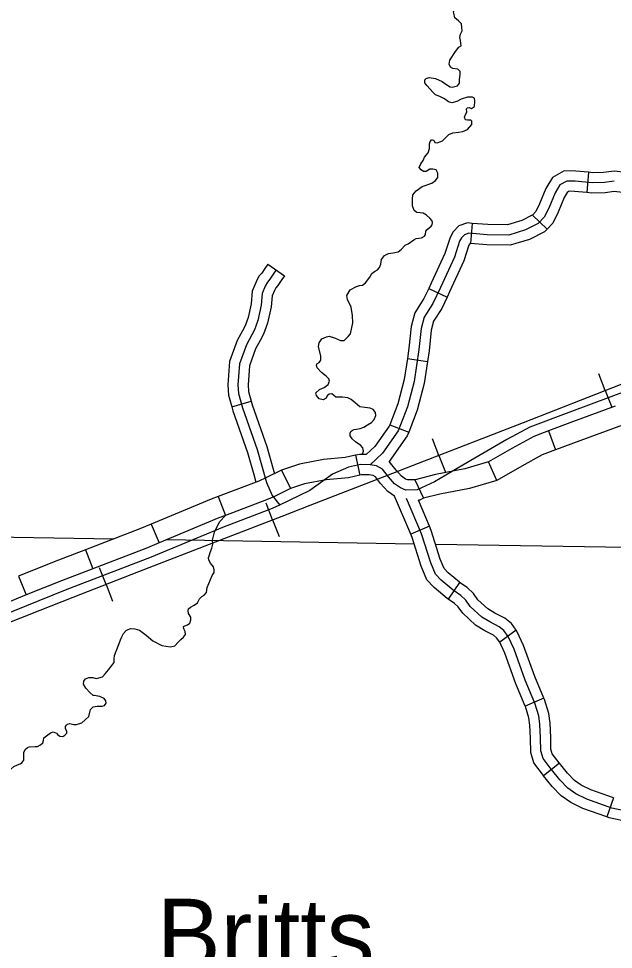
# Model space of a CAD drawing. Extents: x 8749 to 11879, y 13275 to 15339.
# Drawn here: x 10649.1 to 10737.1, y 13692.2 to 13830 of the extents above; entities that cross this region are included whole.
import ezdxf

# ---------------------------------------------------------------- set-up
doc = ezdxf.new("R2010")
doc.units = 0
for name, color, linetype in [('Level 25', 7, 'Continuous'), ('Level 32', 7, 'Continuous'), ('Level 35', 7, 'Continuous'), ('Level 40', 7, 'Continuous'), ('Level 45', 7, 'Continuous'), ('Level 5', 7, 'Continuous')]:
    doc.layers.add(name, color=color, linetype=linetype)

msp = doc.modelspace()

# ---------------------------------------------------------------- linework, layer by layer
at = {"layer": 'Level 32'}
for p, q in [((10733.4, 13807.23), (10733.14, 13804.24)), ((10725.11, 13800.9), (10727.28, 13798.83)), ((10716.19, 13799.68), (10715.95, 13796.69)), ((10709.78, 13790.04), (10712.49, 13788.76)), ((10706.63, 13779.7), (10709.6, 13779.25)), ((10704.02, 13769.85), (10706.82, 13768.77)), ((10727.47, 13768.95), (10728.52, 13766.14)), ((10698.95, 13765.36), (10699.61, 13762.43)), ((10688.02, 13763.15), (10689.33, 13760.43)), ((10707.74, 13761.71), (10709.02, 13759)), ((10678.65, 13759.26), (10679.71, 13756.45)), ((10668.75, 13755.17), (10669.9, 13752.41)), ((10709.89, 13754.85), (10707.13, 13753.68)), ((10659.02, 13751.37), (10660.1, 13748.57)), ((10649.14, 13747.46), (10650.26, 13744.68)), ((10714.34, 13746.54), (10712.65, 13744.06)), ((10722.7, 13739.49), (10720.28, 13737.72)), ((10726.81, 13729.4), (10724.04, 13728.23)), ((10729.11, 13719.77), (10726.77, 13717.9)), ((10737.08, 13714.67), (10736.1, 13711.83))]:
    msp.add_line(p, q, dxfattribs=at)
for points in [[(10733.4, 13807.23), (10731.53, 13807.39), (10729.83, 13807.46), (10728.09, 13806.47), (10727.12, 13804.85), (10726.16, 13802.57), (10725.62, 13801.44), (10725.11, 13800.9)], [(10743.64, 13806.46), (10742.86, 13806.42), (10741.26, 13806.62), (10738.95, 13807.2), (10737.21, 13807.41), (10735.64, 13807.22), (10734.02, 13807.18), (10733.4, 13807.23)], [(10737.21, 13805.9), (10735.75, 13805.72), (10733.97, 13805.67), (10731.44, 13805.9), (10730.2, 13805.94), (10729.17, 13805.36), (10728.46, 13804.18), (10727.53, 13801.95), (10726.86, 13800.57), (10725.98, 13799.64), (10724.11, 13798.71), (10721.62, 13797.95), (10718.43, 13798), (10715.72, 13798.22), (10715.05, 13798), (10714.61, 13797.55), (10714.34, 13797.02), (10713.58, 13794.66), (10711.5, 13790.17), (10710.39, 13787.81), (10709.1, 13785.81), (10708.65, 13784.12), (10708.34, 13781), (10707.63, 13776.29), (10706.65, 13772.51), (10705.28, 13768.95), (10702.96, 13765.66), (10701.1, 13763.94)], [(10733.14, 13804.24), (10731.35, 13804.4), (10730.57, 13804.43), (10730.26, 13804.25), (10729.8, 13803.5), (10728.9, 13801.34), (10728.11, 13799.71), (10727.28, 13798.83)], [(10743.8, 13803.47), (10742.76, 13803.41), (10740.71, 13803.66), (10738.41, 13804.24), (10737.21, 13804.39), (10735.86, 13804.22), (10733.92, 13804.17), (10733.14, 13804.24)], [(10725.11, 13800.9), (10725.07, 13800.87), (10723.55, 13800.11), (10721.41, 13799.45), (10718.5, 13799.5), (10716.19, 13799.68)], [(10716.19, 13799.68), (10715.53, 13799.74), (10714.24, 13799.31), (10713.37, 13798.44), (10712.95, 13797.59), (10712.18, 13795.21), (10710.14, 13790.81), (10709.78, 13790.04)], [(10727.28, 13798.83), (10726.88, 13798.42), (10724.67, 13797.31), (10721.84, 13796.45), (10718.35, 13796.5), (10715.95, 13796.69)], [(10715.95, 13796.69), (10715.9, 13796.7), (10715.86, 13796.69), (10715.84, 13796.66), (10715.73, 13796.45), (10714.98, 13794.11), (10712.85, 13789.54), (10712.49, 13788.76)], [(10687.2, 13792.78), (10686.79, 13792.18), (10686.29, 13791.4), (10685.92, 13790.99), (10685.6, 13790.4), (10685.14, 13789.3), (10685, 13787.55), (10684.5, 13785.31), (10684, 13783.91), (10682.81, 13781.71), (10681.8, 13778.91), (10681.57, 13775.8), (10681.66, 13774.51), (10682.26, 13772.36), (10684.41, 13766.22), (10685.78, 13761.32), (10686.65, 13759.39), (10687.78, 13757.99)], [(10709.78, 13790.04), (10709.07, 13788.54), (10707.71, 13786.43), (10707.17, 13784.39), (10706.85, 13781.19), (10706.63, 13779.7)], [(10712.49, 13788.76), (10711.7, 13787.09), (10710.49, 13785.2), (10710.13, 13783.86), (10709.83, 13780.81), (10709.6, 13779.25)], [(10706.63, 13779.7), (10706.16, 13776.59), (10705.22, 13772.97), (10704.02, 13769.85)], [(10709.6, 13779.25), (10709.1, 13775.99), (10708.09, 13772.05), (10706.82, 13768.77)], [(10737.36, 13772.63), (10731.05, 13770.29), (10727.47, 13768.95)], [(10704.02, 13769.85), (10703.95, 13769.66), (10701.82, 13766.65), (10700.54, 13765.46)], [(10738.41, 13769.82), (10732.1, 13767.48), (10728.52, 13766.14)], [(10706.82, 13768.77), (10706.61, 13768.24), (10703.95, 13764.45)], [(10727.47, 13768.95), (10725.33, 13768.15), (10722.06, 13766.38), (10718.63, 13764.4)], [(10698.93, 13765.35), (10697.44, 13765.01), (10694.2, 13764.71), (10690.66, 13764.06), (10688.02, 13763.15)], [(10700.54, 13765.46), (10699.54, 13765.49), (10698.95, 13765.36)], [(10728.52, 13766.14), (10726.57, 13765.41), (10723.53, 13763.76), (10719.83, 13761.63)], [(10707.75, 13761.72), (10706.68, 13761.71), (10706.36, 13761.84), (10705.74, 13762.27), (10704.96, 13763.13), (10703.95, 13764.45)], [(10718.63, 13764.4), (10715.11, 13763.33), (10710.79, 13762.51), (10707.75, 13761.72)], [(10719.83, 13761.63), (10718.63, 13764.4)], [(10688.03, 13763.13), (10685.71, 13762), (10684.64, 13761.52), (10678.65, 13759.26)], [(10699.61, 13762.43), (10697.92, 13762.04), (10694.61, 13761.74), (10691.42, 13761.15), (10689.33, 13760.43)], [(10704.74, 13759.31), (10703.75, 13760.01), (10702.66, 13761.2), (10701.92, 13762.17), (10701.58, 13762.36), (10700.98, 13762.44), (10699.83, 13762.48), (10699.61, 13762.43)], [(10719.83, 13761.63), (10715.83, 13760.42), (10711.42, 13759.58), (10709.02, 13759)], [(10689.33, 13760.43), (10686.98, 13759.28), (10685.78, 13758.75), (10679.71, 13756.45)], [(10678.65, 13759.26), (10677.63, 13758.87), (10668.75, 13755.17)], [(10707.13, 13753.68), (10704.74, 13759.31)], [(10727.9, 13718.89), (10726.68, 13720.5), (10726.37, 13721.61), (10726.32, 13723.53), (10726.23, 13725.57), (10726.06, 13726.82), (10725.48, 13728.68), (10724.06, 13732.06), (10722.41, 13736.64), (10721.53, 13738.55), (10720.9, 13739.4), (10720.19, 13739.98), (10718.82, 13740.69), (10717.62, 13741.41), (10715.93, 13742.97), (10715.26, 13743.9), (10714.51, 13744.61), (10713.4, 13745.37), (10711.62, 13746.88), (10710.78, 13747.77), (10710.07, 13749.46), (10708.73, 13753.73), (10706.51, 13758.97)], [(10709.02, 13759), (10708.44, 13758.73), (10708.25, 13758.72)], [(10709.89, 13754.85), (10708.25, 13758.72)], [(10679.71, 13756.45), (10678.74, 13756.09), (10669.9, 13752.41)], [(10668.75, 13755.17), (10667.05, 13754.47), (10659.02, 13751.37)], [(10714.34, 13746.54), (10714.31, 13746.56), (10712.65, 13747.97), (10712.05, 13748.6), (10711.48, 13749.97), (10710.14, 13754.24), (10709.89, 13754.85)], [(10712.65, 13744.06), (10712.49, 13744.17), (10710.59, 13745.79), (10709.5, 13746.94), (10708.66, 13748.94), (10707.32, 13753.21), (10707.13, 13753.68)], [(10659.02, 13751.37), (10655.68, 13750.08), (10654.37, 13749.57), (10649.14, 13747.46)], [(10669.9, 13752.41), (10668.17, 13751.68), (10660.1, 13748.57)], [(10660.1, 13748.57), (10656.77, 13747.29), (10655.48, 13746.79), (10650.26, 13744.68)], [(10722.7, 13739.49), (10722, 13740.44), (10721.02, 13741.24), (10719.55, 13742), (10718.52, 13742.62), (10717.06, 13743.97), (10716.4, 13744.89), (10715.45, 13745.79), (10714.34, 13746.54)], [(10650.26, 13744.68), (10645.83, 13742.88), (10641.16, 13740.95), (10640.65, 13740.82)], [(10720.28, 13737.72), (10719.81, 13738.35), (10719.37, 13738.71), (10718.08, 13739.38), (10716.71, 13740.21), (10714.8, 13741.97), (10714.13, 13742.91), (10713.57, 13743.44), (10712.65, 13744.06)], [(10726.81, 13729.4), (10725.46, 13732.61), (10723.8, 13737.21), (10722.82, 13739.32), (10722.7, 13739.49)], [(10724.04, 13728.23), (10722.66, 13731.52), (10721.02, 13736.07), (10720.23, 13737.78), (10720.28, 13737.72)], [(10729.11, 13719.77), (10729.08, 13719.82), (10728.05, 13721.18), (10727.86, 13721.84), (10727.82, 13723.58), (10727.73, 13725.71), (10727.52, 13727.14), (10726.89, 13729.2), (10726.81, 13729.4)], [(10726.77, 13717.9), (10726.75, 13717.93), (10726.73, 13717.95), (10725.31, 13719.82), (10724.87, 13721.39), (10724.82, 13723.48), (10724.74, 13725.43), (10724.59, 13726.49), (10724.07, 13728.17), (10724.04, 13728.23)], [(10737.08, 13714.67), (10733.73, 13715.83), (10732.32, 13716.53), (10731.33, 13717.23), (10730.28, 13718.31), (10729.11, 13719.77)], [(10742.21, 13712), (10736.88, 13713.15), (10733.14, 13714.44), (10731.55, 13715.24), (10730.35, 13716.09), (10729.16, 13717.32), (10727.91, 13718.87), (10727.9, 13718.89)], [(10736.1, 13711.83), (10732.56, 13713.06), (10730.77, 13713.95), (10729.37, 13714.94), (10728.03, 13716.33), (10726.77, 13717.9)], [(10746.16, 13709.08), (10745.87, 13709.2), (10741.81, 13710.55), (10736.47, 13711.71), (10736.1, 13711.83)]]:
    msp.add_lwpolyline(points, dxfattribs=at)
at = {"layer": 'Level 35'}
for points in [[(10714.59, 13825.95), (10714.46, 13826.72), (10714.39, 13827.2), (10714.49, 13827.69), (10714.74, 13828.19), (10714.69, 13828.67), (10714.64, 13829.23), (10714.16, 13829.64), (10713.65, 13830.09), (10713.48, 13830.78), (10713.45, 13830.98), (10713.73, 13831.74), (10713.65, 13832.6), (10713.58, 13833.66), (10713.38, 13834.15), (10713, 13834.6), (10712.54, 13834.78), (10712.21, 13834.78), (10711.78, 13834.68), (10711.27, 13834.15), (10710.67, 13833.72), (10710.19, 13833.61), (10709.65, 13833.74), (10709.43, 13834.11)], [(10709.22, 13820.46), (10709.22, 13820.91), (10709.4, 13821.13), (10709.86, 13821.26), (10710.79, 13821.11), (10711.78, 13820.68), (10712.31, 13820.3), (10712.97, 13819.87), (10713.27, 13819.82), (10714.03, 13820.02), (10714.31, 13820.42), (10714.34, 13821.03), (10714.36, 13821.26), (10714.44, 13821.79), (10714.41, 13822.15), (10714.06, 13822.48), (10713.35, 13822.58), (10713, 13822.78), (10712.82, 13823.26), (10712.89, 13823.84), (10713.75, 13825.11), (10714.24, 13825.74), (10714.59, 13825.95)], [(10716.24, 13818.36), (10715.5, 13818.36), (10714.59, 13818.06), (10713.96, 13817.7), (10713.2, 13817.5), (10712.69, 13817.68), (10712.13, 13818.13), (10711.43, 13818.44), (10710.77, 13818.71), (10710.41, 13819.07), (10709.98, 13819.55), (10709.48, 13820.06), (10709.22, 13820.46)], [(10716.09, 13816.68), (10716.54, 13816.97), (10716.59, 13817.78), (10716.54, 13818.21), (10716.24, 13818.36)], [(10708.36, 13807.96), (10708.62, 13808.5), (10708.95, 13808.99), (10709.15, 13809.47), (10709.71, 13810.13), (10709.88, 13810.76), (10709.88, 13811.47), (10710.01, 13811.8), (10710.21, 13812.03), (10710.34, 13812.05), (10710.51, 13811.98), (10710.69, 13811.65), (10711.05, 13811.62), (10711.81, 13811.9), (10712.34, 13812.41), (10712.74, 13812.81), (10713.32, 13813.09), (10714.19, 13813.17), (10714.84, 13813.27), (10715.53, 13813.57), (10716.16, 13814.33), (10716.16, 13814.79), (10716.01, 13814.94), (10715.53, 13814.96), (10715.22, 13815.02), (10715.07, 13815.4), (10715.2, 13815.8), (10715.4, 13816.13), (10715.37, 13816.64), (10715.53, 13816.79), (10715.75, 13816.81), (10716.09, 13816.68)], [(10825.33, 13808.7), (10800.47, 13798.96), (10783.63, 13792.51), (10764.53, 13785.06), (10751.58, 13779.81), (10739.63, 13775.07), (10730.52, 13771.69), (10724.71, 13769.52), (10721.33, 13767.69), (10714.8, 13763.91), (10710.63, 13761.42), (10708.09, 13760.22), (10706.39, 13760.2)], [(10709.28, 13798.01), (10709.33, 13798.51), (10709.53, 13798.76), (10710.14, 13799.24), (10710.31, 13799.47), (10710.34, 13799.8), (10710.31, 13800.05), (10709.96, 13800.46), (10709.45, 13800.89), (10708.97, 13801.17), (10708.52, 13801.24), (10708.03, 13801.29), (10707.65, 13801.6), (10707.4, 13802.28), (10707.38, 13803.27), (10707.43, 13803.9), (10707.93, 13804.49), (10708.79, 13805.12), (10710.24, 13805.63), (10710.77, 13806.03), (10711.12, 13806.46), (10711.15, 13807.1), (10710.87, 13807.6), (10710.39, 13807.7), (10709.96, 13807.68), (10709.38, 13807.37), (10709.02, 13807.35), (10708.64, 13807.6), (10708.36, 13807.96)], [(10701.35, 13792.26), (10701.74, 13792.57), (10702.22, 13792.82), (10702.5, 13793.15), (10702.68, 13793.66), (10702.8, 13794.34), (10703.23, 13794.92), (10703.84, 13795.23), (10704.52, 13795.3), (10705.26, 13795.48), (10705.69, 13795.81), (10706.3, 13796.44), (10706.73, 13796.64), (10707.56, 13797.25), (10707.92, 13797.46), (10708.73, 13797.56), (10709.13, 13797.78), (10709.28, 13798.01)], [(10693.56, 13779.11), (10693.82, 13779.43), (10693.84, 13780.01), (10693.46, 13781.46), (10693.59, 13782.02), (10693.99, 13782.57), (10694.65, 13782.9), (10695.08, 13782.98), (10695.87, 13782.73), (10696.75, 13782.32), (10697.26, 13782.35), (10697.87, 13782.95), (10698.22, 13783.31), (10698.55, 13784.98), (10698.5, 13786.02), (10698.32, 13787.26), (10697.77, 13788.4), (10697.66, 13789.01), (10698.15, 13789.84), (10699.11, 13790.35), (10699.56, 13790.5), (10699.97, 13790.55), (10700.42, 13790.86), (10701.06, 13791.72), (10701.35, 13792.26)], [(10701.71, 13770.64), (10701.97, 13771.23), (10701.89, 13771.69), (10701.56, 13772.12), (10701.13, 13772.35), (10700.32, 13772.45), (10699.61, 13772.53), (10698.9, 13773.13), (10698.32, 13773.62), (10697.84, 13773.87), (10697.01, 13773.97), (10696.04, 13773.97), (10695.72, 13774.27), (10695.46, 13774.45), (10695.08, 13774.38), (10694.78, 13774.15), (10694.6, 13773.82), (10694.17, 13773.54), (10693.59, 13773.69), (10693.16, 13774.22), (10693.08, 13774.58), (10693.61, 13775.08), (10694.3, 13775.39), (10694.91, 13775.84), (10695.11, 13776.33), (10695.01, 13776.68), (10694.63, 13777.04), (10693.94, 13777.62), (10693.29, 13778.3), (10693.16, 13778.66), (10693.21, 13778.91), (10693.56, 13779.11)], [(10700, 13765.59), (10700.12, 13765.95), (10700.02, 13766.48), (10699.69, 13766.86), (10699.13, 13767.19), (10698.93, 13767.34), (10698.45, 13767.8), (10698.17, 13768.21), (10698.17, 13768.61), (10698.27, 13768.86), (10698.5, 13769.09), (10698.75, 13769.19), (10699.08, 13769.24), (10699.64, 13769.32), (10700.2, 13769.52), (10700.75, 13769.88), (10701.31, 13770.23), (10701.71, 13770.64)], [(10706.39, 13760.2), (10705.63, 13760.52), (10704.74, 13761.14), (10703.81, 13762.16), (10702.92, 13763.32), (10702.08, 13763.81), (10701.1, 13763.94), (10699.68, 13763.98), (10697.9, 13763.58), (10695.55, 13762.56), (10692.22, 13760.16), (10687.61, 13757.93), (10686.36, 13757.36), (10679.29, 13754.69), (10668.72, 13750.29), (10657.31, 13745.89)], [(10677.8, 13752.78), (10678.08, 13753.98), (10678.86, 13755.5), (10679.8, 13756.49)], [(10673.55, 13739.67), (10673.52, 13740.01), (10673.73, 13740.11), (10674.1, 13740.26), (10674.43, 13740.49), (10674.61, 13741), (10674.61, 13741.38), (10674.26, 13741.96), (10674.21, 13742.36), (10674.28, 13742.62), (10674.56, 13742.9), (10675.09, 13743.15), (10675.57, 13743.5), (10675.9, 13744.11), (10676.21, 13744.47), (10676.59, 13744.64), (10676.94, 13745.07), (10677.04, 13745.81), (10677.52, 13746.95), (10677.75, 13747.58), (10678.03, 13747.99), (10678.03, 13748.39), (10677.95, 13748.85), (10677.5, 13749.41), (10677.27, 13749.81), (10677.22, 13750.19), (10677.34, 13750.6), (10677.47, 13750.98), (10677.72, 13751.59), (10677.85, 13752.19), (10677.8, 13752.78)], [(10657.31, 13745.89), (10656.03, 13745.39), (10646.39, 13741.5)], [(10659.77, 13727.73), (10660.16, 13728.14), (10660.77, 13728.22), (10661.5, 13728.22), (10661.86, 13728.32), (10662.09, 13728.65), (10662.04, 13729.03), (10661.81, 13729.36), (10661.13, 13729.64), (10660.32, 13729.79), (10660.14, 13729.79), (10659.71, 13730.22), (10659.07, 13730.88), (10658.72, 13731.46), (10658.8, 13731.92), (10659.05, 13732.27), (10659.53, 13732.45), (10660.09, 13732.45), (10660.59, 13732.32), (10661.02, 13732.4), (10661.53, 13732.55), (10661.91, 13733.03), (10662.44, 13733.62), (10662.72, 13734), (10663.25, 13734.68), (10663.28, 13735.21), (10663.33, 13735.74), (10663.93, 13737.26), (10664.29, 13738.28), (10664.67, 13738.96), (10665.02, 13739.42), (10665.25, 13739.54), (10665.66, 13739.7), (10666.31, 13739.65), (10667.02, 13739.49), (10667.98, 13738.71), (10669, 13737.9), (10670.31, 13737.19), (10671.58, 13737.01), (10672.24, 13737.14), (10672.72, 13737.72), (10673.1, 13738.07), (10673.5, 13738.43), (10673.81, 13738.81), (10673.76, 13739.27), (10673.55, 13739.67)], [(10649.92, 13720.23), (10649.89, 13720.96), (10649.89, 13721.39), (10650.12, 13721.8), (10650.43, 13722.13), (10650.7, 13722.23), (10651.59, 13722.25), (10651.94, 13722.25), (10652.37, 13722.48), (10652.7, 13722.81), (10652.81, 13723.16), (10652.86, 13723.55), (10653.46, 13723.98), (10653.87, 13724.28), (10654.27, 13724.43), (10654.75, 13724.25), (10654.88, 13724.03), (10655.24, 13723.8), (10655.67, 13723.75), (10655.97, 13723.93), (10656.25, 13724.23), (10656.27, 13724.46), (10656.05, 13724.94), (10656.07, 13725.22), (10656.2, 13725.42), (10656.35, 13725.55), (10656.7, 13725.65), (10657.29, 13725.52), (10657.69, 13725.5), (10658.5, 13725.77), (10658.98, 13726.18), (10659.51, 13726.71), (10659.77, 13727.73)], [(10641.27, 13720.62), (10641.72, 13719.82), (10642.25, 13719.34), (10643.01, 13718.93), (10643.59, 13718.91), (10643.95, 13718.91), (10644.53, 13718.83), (10645.32, 13718.48), (10645.92, 13718), (10646.51, 13717.92), (10647.01, 13717.82), (10647.16, 13717.9), (10647.49, 13718.07), (10647.57, 13718.35), (10647.72, 13718.66), (10647.97, 13718.91), (10648.45, 13719.29), (10648.96, 13719.54), (10649.37, 13719.67), (10649.59, 13719.85), (10649.92, 13720.23)]]:
    msp.add_lwpolyline(points, dxfattribs=at)
at = {"layer": 'Level 40'}
for p, q in [((10735.89, 13774.94), (10734.93, 13777.4)), ((10735.89, 13774.94), (10736.84, 13772.48)), ((10711.29, 13765.34), (10710.34, 13767.81)), ((10711.29, 13765.34), (10712.24, 13762.88)), ((10686.68, 13755.79), (10685.72, 13758.25)), ((10686.68, 13755.79), (10687.64, 13753.33)), ((10662.07, 13746.24), (10661.1, 13748.7)), ((10662.07, 13746.24), (10663.04, 13743.79))]:
    msp.add_line(p, q, dxfattribs=at)
for points in [[(10747, 13779.26), (10733.3, 13773.93), (10723.75, 13770.14), (10708.22, 13764.16), (10703.54, 13762.32), (10692.19, 13757.94), (10688.04, 13756.32), (10678.82, 13752.73), (10666.84, 13748.13), (10657.15, 13744.3), (10652.29, 13742.36), (10608.58, 13725.05)], [(10747, 13779.26), (10733.3, 13773.93), (10723.75, 13770.14), (10708.22, 13764.16), (10703.54, 13762.32), (10692.19, 13757.94), (10688.04, 13756.32), (10678.82, 13752.73), (10666.84, 13748.13), (10657.15, 13744.3), (10652.29, 13742.36)]]:
    msp.add_lwpolyline(points, dxfattribs=at)
at = {"layer": 'Level 45'}
for p, q in [((10685.97, 13793.63), (10688.44, 13791.92)), ((10680.65, 13772.54), (10683.54, 13773.34))]:
    msp.add_line(p, q, dxfattribs=at)
for points in [[(10685.97, 13793.63), (10685.54, 13793.02), (10685.09, 13792.31), (10684.68, 13791.86), (10684.24, 13791.04), (10683.67, 13789.65), (10683.52, 13787.78), (10683.06, 13785.73), (10682.62, 13784.52), (10682.23, 13783.78)], [(10688.44, 13791.92), (10688.04, 13791.35), (10687.48, 13790.49), (10687.16, 13790.13), (10686.96, 13789.75), (10686.62, 13788.94), (10686.49, 13787.33), (10685.94, 13784.89), (10685.37, 13783.29), (10684.86, 13782.36)], [(10682.23, 13783.78), (10681.43, 13782.32), (10680.32, 13779.23), (10680.07, 13775.8), (10680.18, 13774.26), (10680.65, 13772.54)], [(10684.86, 13782.36), (10684.18, 13781.09), (10683.28, 13778.6), (10683.08, 13775.79), (10683.15, 13774.77), (10683.54, 13773.34)], [(10683.54, 13773.34), (10683.69, 13772.81), (10685.84, 13766.67), (10686.78, 13763.3)], [(10680.65, 13772.54), (10680.83, 13771.91), (10682.98, 13765.77), (10683.9, 13762.49)], [(10683.9, 13762.49), (10684.21, 13761.36)], [(10686.78, 13763.3), (10686.98, 13762.62)]]:
    msp.add_lwpolyline(points, dxfattribs=at)
at = {"layer": 'Level 5'}
for points in [[(10636.53, 13753.44), (10663.23, 13753)], [(10671.01, 13752.87), (10707.62, 13752.26)], [(10710.78, 13752.21), (10742.23, 13751.69)]]:
    msp.add_lwpolyline(points, dxfattribs=at)

# ---------------------------------------------------------------- texts
at = {"layer": 'Level 25'}
msp.add_text('Britts', height=10.56, dxfattribs=at).set_placement((10669.58, 13689.17))

doc.saveas('drawing.dxf')
